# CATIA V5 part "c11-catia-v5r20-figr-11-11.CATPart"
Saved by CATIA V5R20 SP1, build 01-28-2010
Part number: Part1
Bounding box of the stored display mesh (mm): x -10 to 5, y -10.258 to 7.91, z -1.915 to 2.054
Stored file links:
  D:\v5_r20\psrt_files_downloaded\c11\c11-catia-v5r20-figr-11-11.CATPart
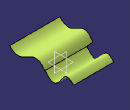
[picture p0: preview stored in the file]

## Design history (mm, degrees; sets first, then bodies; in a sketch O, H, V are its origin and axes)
Set1
  Sketch1 on yz-plane, origin (0, 0, 0), H (0, 1, 0), V (0, 0, 1)
    spline S1 through (-0.358, 0) (-3.1664, 2.0538) (-6.7822, 0.4079) (-10.2576, 1.6423)
    point P1 (-0.358, 0)
    coincidence: P1 H
  Extrude1: Element1 Sketch1, Lim1 5, Lim2 10, Direction yz-plane
  Sketch2 on yz-plane, origin (0, 0, 0), H (0, 1, 0), V (0, 0, 1)
    spline S1 through (0, 0) (3.5471, -1.4404) (5.7957, 1.2855) (7.9098, 0)
    point P1 (0, 0)
    point P2 (7.9098, 0)
    coincidence: P1 O, P2 H
  Extrude2: Element1 Sketch2, Lim1 4, Lim2 8, Direction yz-plane
  Healing1: BodyToHeal (Extrude2; Extrude1), TangencyAngle 0.5, SharpnessAngle 0.5
Body1 (main body)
